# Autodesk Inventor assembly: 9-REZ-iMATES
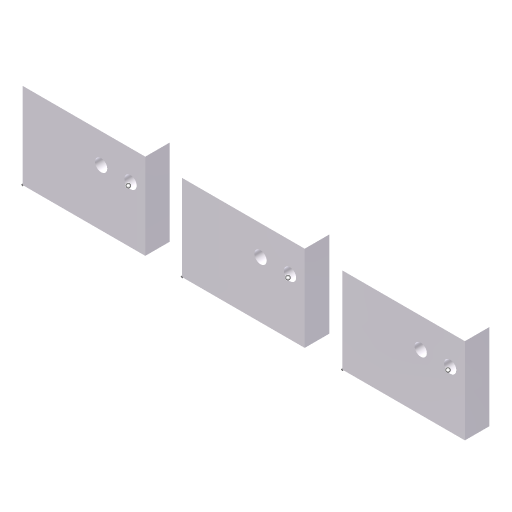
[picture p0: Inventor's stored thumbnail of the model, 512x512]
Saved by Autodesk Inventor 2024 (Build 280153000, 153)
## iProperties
Created: 2023-03
Part Number: 9-REZ-iMATES
Document SubType Name: Assembly
Designer: Andrzej Jaskulski
Manufacturer: Standard
Standards Organization: Custom
Checked By: A.J.
Engr Approved By: Andrzej Jaskulski
Mfg Approved By: Andrzej Jaskulski
Authority: A.J.
Company: ATC
Title: A.J.: Kurs R2024-MEP
Author: Andrzej Jaskulski
Revision Number: 1/24
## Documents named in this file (2)
- C:\Users\AndJas\Documents\R2024-MEP\Obszar roboczy\9-REZ-iMATES.iam
- C:\Users\AndJas\Documents\R2024-MEP\Obszar roboczy\9-REZ-iMATE-BAZA.ipt
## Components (3 placed, 1 different names)
1. 9-REZ-iMATE-BAZA:1
2. 9-REZ-iMATE-BAZA:2
3. 9-REZ-iMATE-BAZA:3
